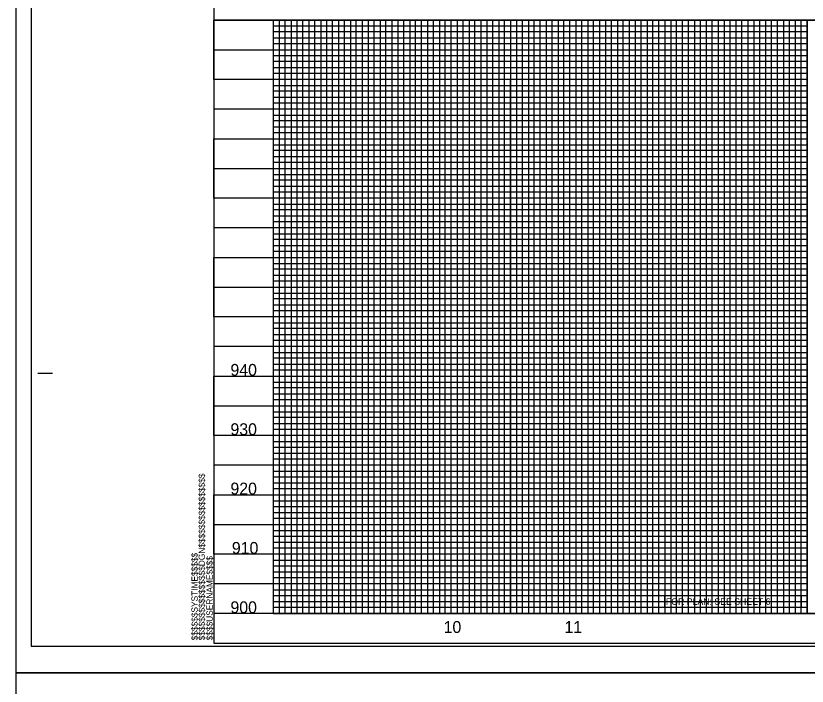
# Model space of a CAD drawing. Extents: x 1967929 to 1975641, y 546296 to 568534.
# Drawn here: x 1969864 to 1970531, y 565223 to 565787 of the extents above; entities that cross this region are included whole.
import ezdxf

# ---------------------------------------------------------------- set-up
doc = ezdxf.new("R2010")
doc.units = 0
for name, color, linetype in [('Exist Vertical Profile Horizontal Axis Label Major', 7, 'Continuous'), ('Exist Vertical Profile Vertical Axis Label', 7, 'Continuous'), ('Old_Level_41', 7, 'Continuous'), ('Old_Level_43', 7, 'Continuous'), ('Old_Level_46', 7, 'Continuous'), ('Prop Grid Mask', 7, 'Continuous'), ('Scratch_Level_3', 7, 'Continuous'), ('Sheet Cutting Line CELL', 7, 'Continuous'), ('Sheet Plot Border Inside CELL', 7, 'Continuous'), ('Sheet Plot Border Outside CELL', 7, 'Continuous'), ('Sheet Profile CELL', 7, 'Continuous'), ('Sheet Profile Grid Major CELL', 7, 'Continuous'), ('Sheet Profile Grid Middle CELL', 7, 'Continuous'), ('Sheet Profile Grid Minor CELL', 7, 'Continuous')]:
    doc.layers.add(name, color=color, linetype=linetype)

msp = doc.modelspace()

# ---------------------------------------------------------------- linework, layer by layer
at = {"layer": 'Old_Level_41'}
msp.add_line((1969882.95, 565486.36), (1969895.45, 565486.36), dxfattribs=at)
at = {"layer": 'Old_Level_43'}
msp.add_line((1970081.45, 565673.86), (1970081.45, 565673.86), dxfattribs=at)
at = {"layer": 'Old_Level_46'}
for p, q in [((1970031.45, 565683.86), (1970031.45, 565683.86)), ((1970531.45, 565683.86), (1970531.45, 565683.86))]:
    msp.add_line(p, q, dxfattribs=at)
at = {"layer": 'Prop Grid Mask'}
msp.add_lwpolyline([(1970411.53, 565298.9), (1970526.41, 565298.9), (1970526.41, 565288.87), (1970411.53, 565288.87)], close=True, dxfattribs=at)
at = {"layer": 'Scratch_Level_3'}
for points in [[(1970081.45, 565783.86), (1970081.45, 565283.86), (1971481.45, 565283.86), (1971481.45, 565783.86)], [(1970081.45, 565783.86), (1970081.45, 565283.86), (1971381.45, 565283.86), (1971381.45, 565783.86)], [(1970081.45, 565783.86), (1970081.45, 565283.86), (1971481.45, 565283.86), (1971481.45, 565783.86)], [(1970081.45, 565283.86), (1970281.45, 565283.86), (1970281.45, 565733.86), (1970081.45, 565733.86)]]:
    msp.add_lwpolyline(points, close=True, dxfattribs=at)
at = {"layer": 'Sheet Cutting Line CELL'}
for p, q in [((1969864.45, 566333.86), (1969864.45, 565233.86)), ((1969864.45, 565233.86), (1971548.45, 565233.86)), ((1969864.45, 565233.86), (1969864.45, 564133.86))]:
    msp.add_line(p, q, dxfattribs=at)
at = {"layer": 'Sheet Plot Border Inside CELL'}
msp.add_lwpolyline([(1969877.45, 565256.31), (1971543.95, 565256.31), (1971543.95, 566311.41), (1969877.45, 566311.41)], close=True, dxfattribs=at)
at = {"layer": 'Sheet Plot Border Outside CELL'}
for points in [[(1969864.45, 565233.86), (1971548.45, 565233.86), (1971548.45, 566333.86), (1969864.45, 566333.86)], [(1969864.45, 564133.86), (1971548.45, 564133.86), (1971548.45, 565233.86), (1969864.45, 565233.86)]]:
    msp.add_lwpolyline(points, close=True, dxfattribs=at)
at = {"layer": 'Sheet Profile CELL'}
for p, q in [((1971531.45, 565783.86), (1970031.45, 565783.86)), ((1971531.45, 565283.86), (1970031.45, 565283.86))]:
    msp.add_line(p, q, dxfattribs=at)
msp.add_lwpolyline([(1971531.45, 566308.86), (1970031.45, 566308.86), (1970031.45, 565258.86), (1971531.45, 565258.86)], close=True, dxfattribs=at)
at = {"layer": 'Sheet Profile Grid Major CELL'}
for points in [[(1970531.45, 565733.86), (1970031.45, 565733.86), (1970031.45, 565783.86), (1971531.45, 565783.86)], [(1970081.45, 565783.86), (1970081.45, 565283.86), (1970131.45, 565283.86), (1970131.45, 565783.86)], [(1970181.45, 565783.86), (1970181.45, 565283.86), (1970231.45, 565283.86), (1970231.45, 565783.86)], [(1970281.45, 565783.86), (1970281.45, 565283.86), (1970331.45, 565283.86), (1970331.45, 565783.86)], [(1970381.45, 565783.86), (1970381.45, 565283.86), (1970431.45, 565283.86), (1970431.45, 565783.86)], [(1970481.45, 565783.86), (1970481.45, 565283.86), (1970531.45, 565283.86), (1970531.45, 565783.86)], [(1970531.45, 565783.86), (1970531.45, 565283.86), (1970581.45, 565283.86), (1970581.45, 565783.86)], [(1970531.45, 565633.86), (1970031.45, 565633.86), (1970031.45, 565683.86), (1970531.45, 565683.86)], [(1970531.45, 565533.86), (1970031.45, 565533.86), (1970031.45, 565583.86), (1970531.45, 565583.86)], [(1970531.45, 565433.86), (1970031.45, 565433.86), (1970031.45, 565483.86), (1970531.45, 565483.86)], [(1970531.45, 565333.86), (1970031.45, 565333.86), (1970031.45, 565383.86), (1970531.45, 565383.86)]]:
    msp.add_lwpolyline(points, dxfattribs=at)
at = {"layer": 'Sheet Profile Grid Middle CELL'}
for points in [[(1970031.45, 565783.86), (1970031.45, 565758.86), (1970531.45, 565758.86)], [(1970106.45, 565283.86), (1970106.45, 565783.86)], [(1970156.45, 565783.86), (1970156.45, 565283.86), (1970206.45, 565283.86), (1970206.45, 565783.86)], [(1970256.45, 565783.86), (1970256.45, 565283.86), (1970306.45, 565283.86), (1970306.45, 565783.86)], [(1970356.45, 565783.86), (1970356.45, 565283.86), (1970406.45, 565283.86), (1970406.45, 565783.86)], [(1970456.45, 565783.86), (1970456.45, 565283.86), (1970506.45, 565283.86), (1970506.45, 565783.86)], [(1970531.45, 565708.86), (1970031.45, 565708.86), (1970031.45, 565658.86), (1970531.45, 565658.86)], [(1970531.45, 565608.86), (1970031.45, 565608.86), (1970031.45, 565558.86), (1970531.45, 565558.86)], [(1970531.45, 565508.86), (1970031.45, 565508.86), (1970031.45, 565458.86), (1970531.45, 565458.86)], [(1970531.45, 565408.86), (1970031.45, 565408.86), (1970031.45, 565358.86), (1970531.45, 565358.86)], [(1970531.45, 565308.86), (1970031.45, 565308.86)]]:
    msp.add_lwpolyline(points, dxfattribs=at)
at = {"layer": 'Sheet Profile Grid Minor CELL'}
for points in [[(1970086.45, 565783.86), (1970086.45, 565283.86), (1970091.45, 565283.86), (1970091.45, 565783.86)], [(1970096.45, 565783.86), (1970096.45, 565283.86), (1970101.45, 565283.86), (1970101.45, 565783.86)], [(1970111.45, 565783.86), (1970111.45, 565283.86), (1970116.45, 565283.86), (1970116.45, 565783.86)], [(1970121.45, 565783.86), (1970121.45, 565283.86), (1970126.45, 565283.86), (1970126.45, 565783.86)], [(1970136.45, 565783.86), (1970136.45, 565283.86), (1970141.45, 565283.86), (1970141.45, 565783.86)], [(1970146.45, 565783.86), (1970146.45, 565283.86), (1970151.45, 565283.86), (1970151.45, 565783.86)], [(1970161.45, 565783.86), (1970161.45, 565283.86), (1970166.45, 565283.86), (1970166.45, 565783.86)], [(1970171.45, 565783.86), (1970171.45, 565283.86), (1970176.45, 565283.86), (1970176.45, 565783.86)], [(1970186.45, 565783.86), (1970186.45, 565283.86), (1970191.45, 565283.86), (1970191.45, 565783.86)], [(1970196.45, 565783.86), (1970196.45, 565283.86), (1970201.45, 565283.86), (1970201.45, 565783.86)], [(1970211.45, 565783.86), (1970211.45, 565283.86), (1970216.45, 565283.86), (1970216.45, 565783.86)], [(1970221.45, 565783.86), (1970221.45, 565283.86), (1970226.45, 565283.86), (1970226.45, 565783.86)], [(1970236.45, 565783.86), (1970236.45, 565283.86), (1970241.45, 565283.86), (1970241.45, 565783.86)], [(1970246.45, 565283.86), (1970251.45, 565283.86), (1970251.45, 565783.86)], [(1970246.45, 565783.86), (1970246.45, 565283.86)], [(1970261.45, 565783.86), (1970261.45, 565283.86), (1970266.45, 565283.86), (1970266.45, 565783.86)], [(1970271.45, 565783.86), (1970271.45, 565283.86), (1970276.45, 565283.86), (1970276.45, 565783.86)], [(1970286.45, 565783.86), (1970286.45, 565283.86), (1970291.45, 565283.86), (1970291.45, 565783.86)], [(1970296.45, 565783.86), (1970296.45, 565283.86), (1970301.45, 565283.86), (1970301.45, 565783.86)], [(1970311.45, 565783.86), (1970311.45, 565283.86), (1970316.45, 565283.86), (1970316.45, 565783.86)], [(1970321.45, 565783.86), (1970321.45, 565283.86), (1970326.45, 565283.86), (1970326.45, 565783.86)], [(1970336.45, 565783.86), (1970336.45, 565283.86), (1970341.45, 565283.86), (1970341.45, 565783.86)], [(1970346.45, 565783.86), (1970346.45, 565283.86), (1970351.45, 565283.86), (1970351.45, 565783.86)], [(1970361.45, 565783.86), (1970361.45, 565283.86), (1970366.45, 565283.86), (1970366.45, 565783.86)], [(1970371.45, 565783.86), (1970371.45, 565283.86), (1970376.45, 565283.86), (1970376.45, 565783.86)], [(1970386.45, 565783.86), (1970386.45, 565283.86), (1970391.45, 565283.86), (1970391.45, 565783.86)], [(1970396.45, 565783.86), (1970396.45, 565283.86), (1970401.45, 565283.86), (1970401.45, 565783.86)], [(1970411.45, 565783.86), (1970411.45, 565283.86), (1970426.45, 565283.86), (1970426.45, 565783.86)], [(1970416.45, 565783.86), (1970416.45, 565283.86), (1970421.45, 565283.86), (1970421.45, 565783.86)], [(1970436.45, 565783.86), (1970436.45, 565283.86), (1970441.45, 565283.86), (1970441.45, 565783.86)], [(1970446.45, 565783.86), (1970446.45, 565283.86), (1970451.45, 565283.86), (1970451.45, 565783.86)], [(1970461.45, 565783.86), (1970461.45, 565283.86), (1970466.45, 565283.86), (1970466.45, 565783.86)], [(1970471.45, 565783.86), (1970471.45, 565283.86), (1970476.45, 565283.86), (1970476.45, 565783.86)], [(1970486.45, 565783.86), (1970486.45, 565283.86), (1970491.45, 565283.86), (1970491.45, 565783.86)], [(1970496.45, 565783.86), (1970496.45, 565283.86), (1970501.45, 565283.86), (1970501.45, 565783.86)], [(1970511.45, 565783.86), (1970511.45, 565283.86), (1970516.45, 565283.86), (1970516.45, 565783.86)], [(1970521.45, 565783.86), (1970521.45, 565283.86), (1970526.45, 565283.86), (1970526.45, 565783.86)], [(1970081.45, 565778.86), (1970531.45, 565778.86)], [(1970531.45, 565773.86), (1970081.45, 565773.86), (1970081.45, 565768.86), (1970531.45, 565768.86)], [(1970531.45, 565763.86), (1970081.45, 565763.86), (1970081.45, 565753.86), (1970531.45, 565753.86)], [(1970531.45, 565748.86), (1970081.45, 565748.86), (1970081.45, 565743.86), (1970531.45, 565743.86)], [(1970531.45, 565738.86), (1970081.45, 565738.86), (1970081.45, 565728.86), (1970531.45, 565728.86)], [(1970531.45, 565723.86), (1970081.45, 565723.86), (1970081.45, 565718.86), (1970531.45, 565718.86)], [(1970531.45, 565713.86), (1970081.45, 565713.86), (1970081.45, 565703.86), (1970531.45, 565703.86)], [(1970531.45, 565698.86), (1970081.45, 565698.86), (1970081.45, 565693.86), (1970531.45, 565693.86)], [(1970531.45, 565688.86), (1970081.45, 565688.86), (1970081.45, 565678.86), (1970531.45, 565678.86)], [(1970531.45, 565673.86), (1970081.45, 565673.86), (1970081.45, 565668.86), (1970531.45, 565668.86)], [(1970531.45, 565663.86), (1970081.45, 565663.86), (1970081.45, 565653.86), (1970531.45, 565653.86)], [(1970531.45, 565648.86), (1970081.45, 565648.86), (1970081.45, 565643.86), (1970531.45, 565643.86)], [(1970531.45, 565638.86), (1970081.45, 565638.86), (1970081.45, 565628.86), (1970531.45, 565628.86)], [(1970531.45, 565623.86), (1970081.45, 565623.86), (1970081.45, 565618.86), (1970531.45, 565618.86)], [(1970531.45, 565613.86), (1970081.45, 565613.86), (1970081.45, 565603.86), (1970531.45, 565603.86)], [(1970531.45, 565598.86), (1970081.45, 565598.86), (1970081.45, 565593.86), (1970531.45, 565593.86)], [(1970531.45, 565588.86), (1970081.45, 565588.86), (1970081.45, 565578.86), (1970531.45, 565578.86)], [(1970531.45, 565573.86), (1970081.45, 565573.86), (1970081.45, 565568.86), (1970531.45, 565568.86)], [(1970531.45, 565563.86), (1970081.45, 565563.86), (1970081.45, 565553.86), (1970531.45, 565553.86)], [(1970531.45, 565548.86), (1970081.45, 565548.86), (1970081.45, 565543.86), (1970531.45, 565543.86)], [(1970531.45, 565538.86), (1970081.45, 565538.86), (1970081.45, 565528.86), (1970531.45, 565528.86)], [(1970531.45, 565523.86), (1970081.45, 565523.86), (1970081.45, 565518.86), (1970531.45, 565518.86)], [(1970531.45, 565513.86), (1970081.45, 565513.86), (1970081.45, 565503.86), (1970531.45, 565503.86)], [(1970531.45, 565498.86), (1970081.45, 565498.86), (1970081.45, 565493.86), (1970531.45, 565493.86)], [(1970531.45, 565488.86), (1970081.45, 565488.86)], [(1970081.45, 565478.86), (1970531.45, 565478.86)], [(1970531.45, 565473.86), (1970081.45, 565473.86), (1970081.45, 565468.86), (1970531.45, 565468.86)], [(1970531.45, 565463.86), (1970081.45, 565463.86)], [(1970081.45, 565453.86), (1970531.45, 565453.86)], [(1970531.45, 565448.86), (1970081.45, 565448.86), (1970081.45, 565443.86), (1970531.45, 565443.86)], [(1970531.45, 565438.86), (1970081.45, 565438.86), (1970081.45, 565428.86), (1970531.45, 565428.86)], [(1970531.45, 565423.86), (1970081.45, 565423.86), (1970081.45, 565418.86), (1970531.45, 565418.86)], [(1970531.45, 565413.86), (1970081.45, 565413.86), (1970081.45, 565403.86), (1970531.45, 565403.86)], [(1970531.45, 565398.86), (1970081.45, 565398.86), (1970081.45, 565393.86), (1970531.45, 565393.86)], [(1970531.45, 565388.86), (1970081.45, 565388.86), (1970081.45, 565378.86), (1970531.45, 565378.86)], [(1970531.45, 565373.86), (1970081.45, 565373.86), (1970081.45, 565368.86), (1970531.45, 565368.86)], [(1970531.45, 565363.86), (1970081.45, 565363.86), (1970081.45, 565353.86), (1970531.45, 565353.86)], [(1970531.45, 565348.86), (1970081.45, 565348.86), (1970081.45, 565343.86), (1970531.45, 565343.86)], [(1970531.45, 565338.86), (1970081.45, 565338.86), (1970081.45, 565328.86), (1970531.45, 565328.86)], [(1970531.45, 565323.86), (1970081.45, 565323.86), (1970081.45, 565318.86), (1970531.45, 565318.86)], [(1970531.45, 565313.86), (1970081.45, 565313.86), (1970081.45, 565303.86), (1970531.45, 565303.86)], [(1970531.45, 565298.86), (1970081.45, 565298.86), (1970081.45, 565293.86), (1970531.45, 565293.86)], [(1970531.45, 565288.86), (1970081.45, 565288.86)]]:
    msp.add_lwpolyline(points, dxfattribs=at)

# ---------------------------------------------------------------- texts
at = {"layer": 'Exist Vertical Profile Horizontal Axis Label Major'}
for s, p in [('10', (1970225.03, 565267.47)), ('11', (1970326.87, 565267.47))]:
    msp.add_text(s, height=10, dxfattribs=at).set_placement(p)
at = {"layer": 'Exist Vertical Profile Vertical Axis Label'}
for s, p in [('940', (1970045.36, 565484.11)), ('930', (1970045.36, 565434.11)), ('920', (1970045.36, 565384.11)), ('910', (1970046.56, 565334.11)), ('900', (1970045.36, 565284.11))]:
    msp.add_text(s, height=10, dxfattribs=at).set_placement(p)
at = {"layer": 'Prop Grid Mask'}
msp.add_text('FOR PLAN: SEE SHEET 6', height=5.4932, dxfattribs=at).set_placement((1970412.42, 565291.16))
at = {"layer": 'Sheet Profile CELL'}
for s, p in [('$$$$$$$$$$$$$$$$DGN$$$$$$$$$$$$$$$$', (1970023.8, 565261.23)), ('$$$$$$SYSTIME$$$$$', (1970017.75, 565261.23)), ('$$$$USERNAME$$$$', (1970030.37, 565261.24))]:
    msp.add_text(s, height=5.25, rotation=90, dxfattribs=at).set_placement(p)

doc.saveas('drawing.dxf')
